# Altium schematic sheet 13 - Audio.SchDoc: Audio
size A3; PageSetup: Record=PageOptions¦CenterHorizontal=True¦CenterVertical=True¦PrintScale=0.70¦XCorrection=1.00¦YCorrection=1.00¦PrintKind=0¦BorderSize=5000000¦LeftOffset=0¦BottomOffset=0¦Orientation=2¦PaperLength=4200¦PaperWidth=2970¦Scale=100¦PaperSource=7¦PrintQuality=600¦MediaType=1¦DitherType=10¦PaperKind=A4¦PrintScaleMode=1; Author: Juan Anzola; SheetNumber: 13; SheetTotal: 17
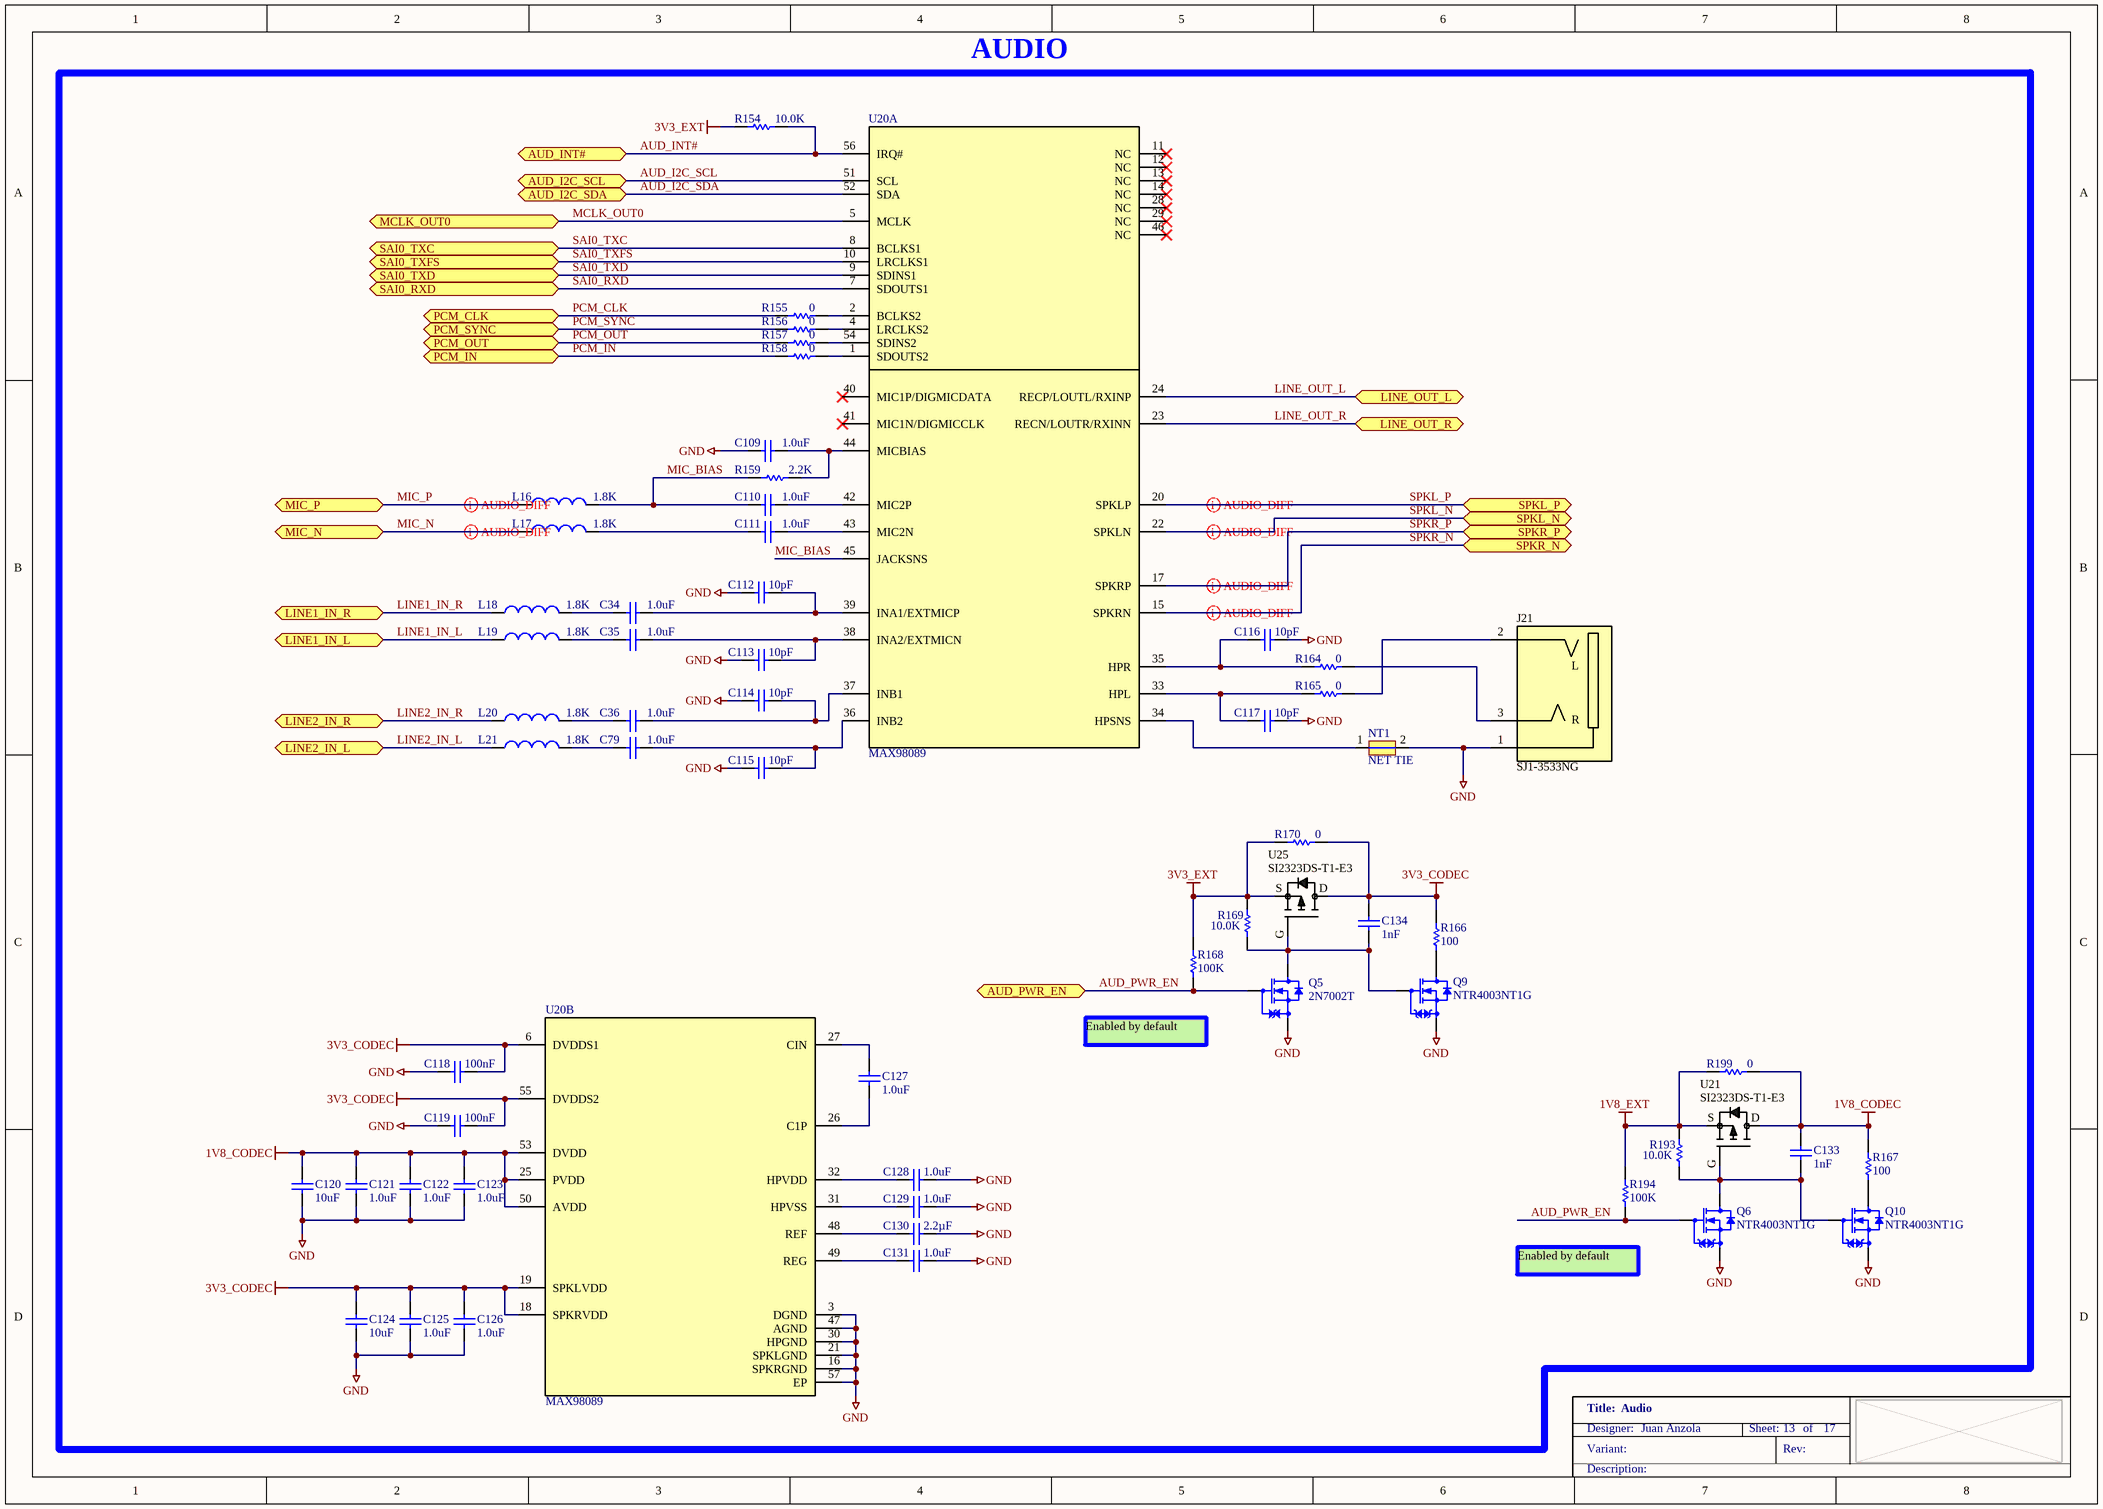
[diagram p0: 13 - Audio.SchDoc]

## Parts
C34  1.0uF  [CAPC1005X55L]
C35  1.0uF  [CAPC1005X55L]
C36  1.0uF  [CAPC1005X55L]
C79  1.0uF  [CAPC1005X55L]
C109  1.0uF  [CAPC1005X55L]
C110  1.0uF  [CAPC1005X55L]
C111  1.0uF  [CAPC1005X55L]
C112  10pF  [CAPC1005X55N]
C113  10pF  [CAPC1005X55N]
C114  10pF  [CAPC1005X55N]
C115  10pF  [CAPC1005X55N]
C116  10pF  [CAPC1005X55N]
C117  10pF  [CAPC1005X55N]
C118  100nF  [CAPC1005X55N]
C119  100nF  [CAPC1005X55N]
C120  10uF  [CAPC1005X55N]
C121  1.0uF  [CAPC1005X55N]
C122  1.0uF  [CAPC1005X55N]
C123  1.0uF  [CAPC1005X55N]
C124  10uF  [CAPC1005X55N]
C125  1.0uF  [CAPC1005X55N]
C126  1.0uF  [CAPC1005X55N]
C127  1.0uF  [CAPC1005X55N]
C128  1.0uF  [CAPC1005X55N]
C129  1.0uF  [CAPC1005X55N]
C130  2.2µF  [CAPC1005X55N]
C131  1.0uF  [CAPC1005X55N]
C133  1nF  [CAPC1005X55N]
C134  1nF  [CAPC1005X55N]
J21  SJ1-3533NG  [CUI_SJ1-3533N]
L16  1.8K  [INDC1005X60N]
L17  1.8K  [INDC1005X60N]
L18  1.8K  [INDC1005X60N]
L19  1.8K  [INDC1005X60N]
L20  1.8K  [INDC1005X60N]
L21  1.8K  [INDC1005X60N]
NT1  NET TIE  [NET_TIE_4mil]  (net tie, no BOM)
Q5  2N7002T  [SOTFL50P160X80_GSD-3N]
Q6  NTR4003NT1G  [SOT95P240X110_GSD-3N]
Q9  NTR4003NT1G  [SOT95P240X110_GSD-3N]
Q10  NTR4003NT1G  [SOT95P240X110_GSD-3N]
R154  10.0K  [RESC1005X40N]
R155  0  [RESC1005X40N]
R156  0  [RESC1005X40N]
R157  0  [RESC1005X40N]
R158  0  [RESC1005X40N]
R159  2.2K  [RESC1005X40N]
R164  0  [RESC1005X40N]
R165  0  [RESC1005X40N]
R166  100  [RESC1005X40N]
R167  100  [RESC1005X40N]
R168  100K  [RESC1005X40N]
R169  10.0K  [RESC1005X40N]
R170  0  [RESC1609X55N]
R193  10.0K  [RESC1005X40N]
R194  100K  [RESC1005X40N]
R199  0  [RESC1609X55N]
U20  MAX98089  [QFN40P700X700X80-57T560X560N]  (parts A,B of 2)
U21  SI2323DS-T1-E3  [SOT95P240X110_GSD-3N]
U25  SI2323DS-T1-E3  [SOT95P240X110_GSD-3N]

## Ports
AUD_I2C_SCL (bidir), AUD_I2C_SDA (bidir), AUD_INT# (bidir), AUD_PWR_EN (bidir), LINE1_IN_L (bidir), LINE1_IN_R (bidir), LINE2_IN_L (bidir), LINE2_IN_R (bidir), LINE_OUT_L (bidir), LINE_OUT_R (bidir), MCLK_OUT0 (bidir), MIC_N (bidir), MIC_P (bidir), PCM_CLK (bidir), PCM_IN (bidir), PCM_OUT (bidir), PCM_SYNC (bidir), SAI0_RXD (bidir), SAI0_TXC (bidir), SAI0_TXD (bidir), SAI0_TXFS (bidir), SPKL_N (bidir), SPKL_P (bidir), SPKR_N (bidir), SPKR_P (bidir)

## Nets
1V8_CODEC: C120.2 C121.1 C122.1 C123.1 C133.2 R167.2 R199.2 U20.25(PVDD) U20.50(AVDD) U20.53(DVDD) U21.D
1V8_EXT: R193.1 R194.1 R199.1 U21.S
3V3_CODEC: C118.1 C119.1 C124.2 C125.1 C126.1 C134.2 R166.2 R170.2 U20.6(DVDDS1) U20.18(SPKRVDD) U20.19(SPKLVDD) U20.55(DVDDS2) U25.D
3V3_EXT: R154.1 R168.1 R169.1 R170.1 U25.S
GND: C109.2 C112.2 C113.2 C114.2 C115.2 C116.2 C117.2 C118.2 C119.2 C120.1 C121.2 C122.2 C123.2 C124.1 C125.2 C126.2 C128.1 C129.1 C130.2 C131.1 J21.1 NT1.2 Q5.S Q6.S Q9.S Q10.S U20.3(DGND) U20.16(SPKRGND) U20.21(SPKLGND) U20.30(HPGND) U20.47(AGND) U20.57(EP)
AUD_I2C_SCL: U20.51(SCL) ; port AUD_I2C_SCL
AUD_I2C_SDA: U20.52(SDA) ; port AUD_I2C_SDA
AUD_INT#: R154.2 U20.56(IRQ#) ; port AUD_INT#
AUD_PWR_EN: Q5.G Q6.G R168.2 R194.2 ; port AUD_PWR_EN
LINE1_IN_L: L19.1 ; port LINE1_IN_L
LINE1_IN_R: L18.1 ; port LINE1_IN_R
LINE2_IN_L: L21.1 ; port LINE2_IN_L
LINE2_IN_R: L20.1 ; port LINE2_IN_R
LINE_OUT_L: U20.24(RECP/LOUTL/RXINP) ; port LINE_OUT_L
LINE_OUT_R: U20.23(RECN/LOUTR/RXINN) ; port LINE_OUT_R
MCLK_OUT0: U20.5(MCLK) ; port MCLK_OUT0
MIC_BIAS: C110.2 L16.2 R159.1 U20.45(JACKSNS)
MIC_N: L17.1 ; port MIC_N
MIC_P: L16.1 ; port MIC_P
PCM_CLK: R155.1 ; port PCM_CLK
PCM_IN: R158.1 ; port PCM_IN
PCM_OUT: R157.1 ; port PCM_OUT
PCM_SYNC: R156.1 ; port PCM_SYNC
SAI0_RXD: U20.7(SDOUTS1) ; port SAI0_RXD
SAI0_TXC: U20.8(BCLKS1) ; port SAI0_TXC
SAI0_TXD: U20.9(SDINS1) ; port SAI0_TXD
SAI0_TXFS: U20.10(LRCLKS1) ; port SAI0_TXFS
SPKL_N: U20.22(SPKLN) ; port SPKL_N
SPKL_P: U20.20(SPKLP) ; port SPKL_P
SPKR_N: U20.15(SPKRN) ; port SPKR_N
SPKR_P: U20.17(SPKRP) ; port SPKR_P
NetC34_1: C34.1 C112.1 U20.39(INA1/EXTMICP)
NetC34_2: C34.2 L18.2
NetC35_1: C35.1 C113.1 U20.38(INA2/EXTMICN)
NetC35_2: C35.2 L19.2
NetC36_1: C36.1 C114.1 U20.37(INB1)
NetC36_2: C36.2 L20.2
NetC79_1: C79.1 C115.1 U20.36(INB2)
NetC79_2: C79.2 L21.2
NetC109_1: C109.1 R159.2 U20.44(MICBIAS)
NetC110_1: C110.1 U20.42(MIC2P)
NetC111_1: C111.1 U20.43(MIC2N)
NetC111_2: C111.2 L17.2
NetC116_1: C116.1 R164.1 U20.35(HPR)
NetC117_1: C117.1 R165.1 U20.33(HPL)
NetC127_1: C127.1 U20.27(CIN)
NetC127_2: C127.2 U20.26(C1P)
NetC128_2: C128.2 U20.32(HPVDD)
NetC129_2: C129.2 U20.31(HPVSS)
NetC130_1: C130.1 U20.48(REF)
NetC131_2: C131.2 U20.49(REG)
NetC133_1: C133.1 Q6.D Q10.G R193.2 U21.G
NetC134_1: C134.1 Q5.D Q9.G R169.2 U25.G
NetJ21_2: J21.2 R165.2
NetJ21_3: J21.3 R164.2
NetNT1_1: NT1.1 U20.34(HPSNS)
NetQ9_D: Q9.D R166.1
NetQ10_D: Q10.D R167.1
NetR155_2: R155.2 U20.2(BCLKS2)
NetR156_2: R156.2 U20.4(LRCLKS2)
NetR157_2: R157.2 U20.54(SDINS2)
NetR158_2: R158.2 U20.1(SDOUTS2)

Not connected (* = marked no-connect by the designer): U20 11(NC)* 12(NC)* 13(NC)* 14(NC)* 28(NC)* 29(NC)* 40(MIC1P/DIGMICDATA)* 41(MIC1N/DIGMICCLK)* 46(NC)*

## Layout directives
differential pair: MIC_N, MIC_P, SPKL_N, SPKL_P, SPKR_N, SPKR_P

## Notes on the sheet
- AUDIO
- Enabled by default

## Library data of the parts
C34-C36 C79 C109-C111 = 1000073: CAP CER 1UF 6.3V 20% X5R 0402; Part_Type: Capacitor; Manufacturer: Murata; Manufacturer_Part_Number: GRM155R60J105ME19D; Digi_PN: 14050543; Component_Life_Cycle_State: Proven; Area: 0.95; Project: Adjustable Foundation
C112-C117 = 1001541: CAP CER 10PF 50V 5% NP0 0402; Part_Type: Capacitor; Manufacturer: Murata; Manufacturer_Part_Number: GRM1555C1H100JA01D; Note: 14050750 = Digi No. for GE WDNU; Digi_PN: 14050362; Component_Life_Cycle_State: Reviewed; Area: 0,95; Project: KITT v0.4; Tolerance: 5; Temp_Coef: C0G, NP0
C118 C119 = 1000918: CAP CER 0.1UF 50V 10% X7R 0402; Part_Type: Capacitor; Manufacturer: TDK Corporation; Manufacturer_Part_Number: C1005X7R1H104K050BB; Digi_PN: 14050715; Component_Life_Cycle_State: Reviewed; Area: 0.95; Project: DTM3.0
C120 C124 = 1001168: CAP CER 10UF 10V 20% X5R 0402; Part_Type: Capacitor; Manufacturer: Samsung; Manufacturer_Part_Number: CL05A106MP5NUNC; Digi_PN: 14050689; Component_Life_Cycle_State: Reviewed; Area: 0.95; Project: CCWMX6_SBC board
C121-C123 C125-C129 C131 = 1001167: CAP CER 1UF 10V 10% X5R 0402; Part_Type: Capacitor; Manufacturer: Murata; Manufacturer_Part_Number: GRM155R61A105KE15D; Digi_PN: 14050399; Component_Life_Cycle_State: Reviewed; Area: 0.95; Project: CCWMX6_SBC board
C130 = 1000970: CAP CER 2.2UF 6.3V 20% X5R 0402; Part_Type: Capacitor; Manufacturer: TDK Corporation; Manufacturer_Part_Number: C1005X5R0J225M050BC; Manufacturer_Alt_1: Taiyo Yuden; Manufacturer_Alt_1_Part_Number: JMK105BJ225MV-F; Note: 14050756 = Digi No. for GE WDNU; Digi_PN: 14050493; Component_Life_Cycle_State: Reviewed; Area: 0,5; Project: ConnectCore i.MX6 module; Tolerance: 20
C133 C134 = 1000067: CAP CER 1000PF 50V 10% X7R 0402; Part_Type: Capacitor; Manufacturer: Murata; Manufacturer_Part_Number: GRM155R71H102KA01D; Digi_PN: 14050737; Component_Life_Cycle_State: Proven; Area: 0,95; Project: Adjustable Foundation
J21 = 1002596: CONN JACK STEREO 3.5MM R/A; Part_Type: Connector; Manufacturer: CUI Inc.; Digi_PN: 18000594; Component_Life_Cycle_State: Reviewed; Area: 163.02; Project: CCWMX6_SBC board
L16-L21 = 1002041: FERRITE BEAD 1.8 KOHM 0402 1LN; Manufacturer: Murata; Manufacturer_Part_Number: BLM15HD182SN1D; Digi_PN: 21000461; Component_Life_Cycle_State: Reviewed; Area: 2.2; Project: iMX6UL+PMIC
NT1 = CAD0044: NET TIE FOR I.MX6x SOM; Component_Life_Cycle_State: Created; Area: 0,039; Project: ConnectCore i.MX6x SOM
Q5 = 1000715: MOSFET N-CH 60V 115MA SOT-523F; Part_Type: Transistor; Manufacturer: Fairchild Semiconductor; Digi_PN: 17050797; Component_Life_Cycle_State: CAD Reviewed; Area: 3.06; Project: SmartMeter2; Note: 17050841 = Digi No. for GE WDNU
Q6 Q9 Q10 = 1000306: MOSFET N-CH 30V 500MA SOT-23; Part_Type: Transistor; Manufacturer: On Semiconductor; Digi_PN: 17050809; Component_Life_Cycle_State: Proven; Area: 10,92; Project: Adjustable Foundation
R154 R169 R193 = 1000537: RES 10.0K OHM 1/10W 1% 0402 SMD; Part_Type: Resistor; Manufacturer: Panasonic - ECG; Manufacturer_Part_Number: ERJ-2RKF1002X; Component_Life_Cycle_State: CAD Reviewed; Area: 0.95; Project: KITT; Power_WV_SRF: 100; Digi_PN: 13051084
R155-R158 R164 R165 = 1000076: RES 0.0 OHM 1/10W 0402 SMD; Part_Type: Resistor; Manufacturer: Panasonic - ECG; Manufacturer_Part_Number: ERJ-2GE0R00X; Component_Life_Cycle_State: Proven; Area: 0.95; Project: Adjustable Foundation; Power_WV_SRF: 10; Digi_PN: 13050387
R159 = 1001156: RES 2.20K OHM 1/16W 1% 0402 SMD; Part_Type: Resistor; Manufacturer: Yageo; Manufacturer_Part_Number: RC0402FR-072K2L; Note: 13051099 = Digi No. for GE WDNU; Digi_PN: 13050699; Component_Life_Cycle_State: Reviewed; Area: 0,95; Project: CCWMX6_SBC board
R166 R167 = 1000467: RES 100 OHM 1/10W 1% 0402 SMD; Part_Type: Resistor; Manufacturer: Panasonic - ECG; Manufacturer_Part_Number: ERJ-2RKF1000X; Digi_PN: 13051087; Component_Life_Cycle_State: CAD Reviewed; Area: 0,95; Project: KITT
R168 R194 = 1000480: RES 100K OHM 1/10W 1% 0402 SMD; Part_Type: Resistor; Manufacturer: Panasonic - ECG; Manufacturer_Part_Number: ERJ-2RKF1003X; Digi_PN: 13051063; Component_Life_Cycle_State: CAD Reviewed; Area: 0.95; Project: KITT; Power_WV_SRF: 100
R170 R199 = 1000208: RES 0.0 OHM 1/10W 0603; Part_Type: Resistor; Manufacturer: Panasonic - ECG; Manufacturer_Part_Number: ERJ-3GEY0R00V; Note: 13051103 = Digi No. for GE WDNU; Digi_PN: 13050568; Component_Life_Cycle_State: Reviewed; Area: 2.5; Project: Adjustable Foundation; Voltage: 75V
U20 = 1002001: IC CODEC AUDIO FLEXSOUND 56TQFN; Manufacturer: Maxim; Manufacturer_Part_Number: MAX98089ETN+T; Component_Life_Cycle_State: Reviewed; Area: 49; Project: iMX6UL+PMIC; Digi_PN: 16052036
U21 U25 = 1001163: MOSFET P-CH 20V 3.7A SOT23-3; Part_Type: IC; Manufacturer: Vishay Siliconix; Digi_PN: 17050358; Component_Life_Cycle_State: Reviewed; Area: 10.92; Project: CCWMX6_SBC board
